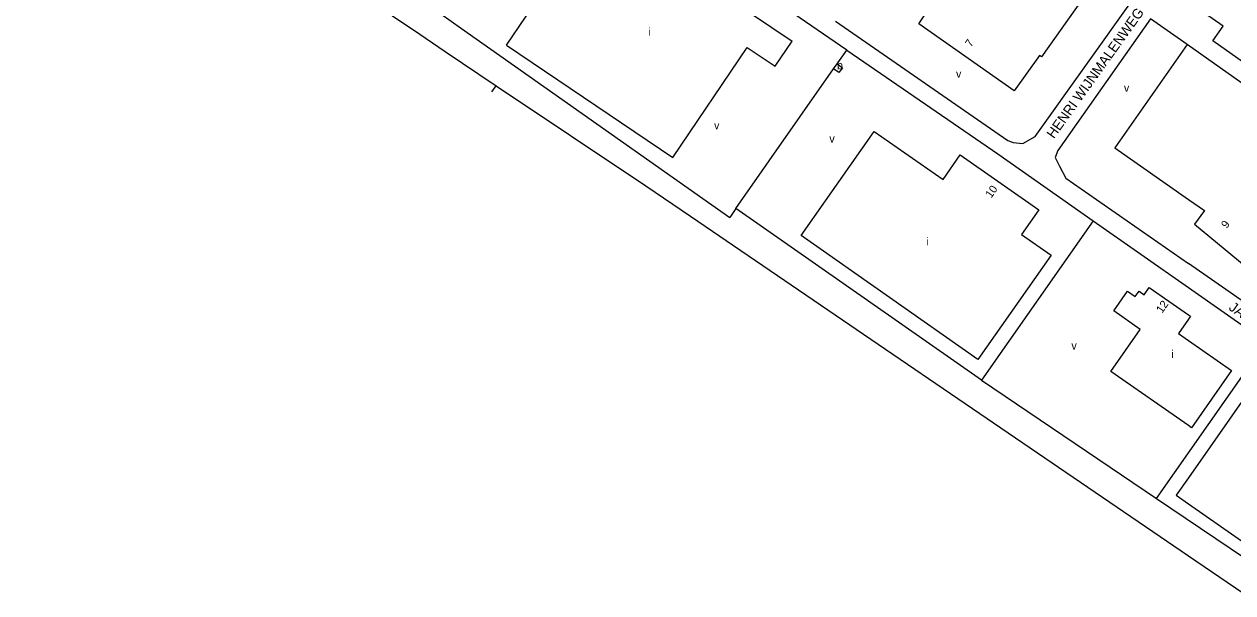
# Model space of a CAD drawing. Extents: x 154765 to 156627, y 383996 to 386132.
# Drawn here: x 154818 to 155422, y 384643 to 384927 of the extents above; entities that cross this region are included whole.
import ezdxf

# ---------------------------------------------------------------- set-up
doc = ezdxf.new("R2010")
doc.units = 0
for name, color, linetype in [('BLT_Basislijn', 7, 'Continuous'), ('BLT_Bebouwing', 7, 'Continuous'), ('BLT_Centroide', 7, 'Continuous'), ('BLT_Huisnummer', 7, 'Continuous'), ('BLT_Huisnummer_reeks', 7, 'Continuous'), ('BLT_Straatnaam', 7, 'Continuous'), ('BLT_Vlakafsluiter', 7, 'Continuous')]:
    doc.layers.add(name, color=color, linetype=linetype)

msp = doc.modelspace()

# ---------------------------------------------------------------- linework, layer by layer
at = {"layer": 'BLT_Basislijn'}
for p, q in [((154818, 385056.39), (155015.72, 384922.31)), ((155229.24, 384914.38), (155092.91, 385008.79)), ((155021.15, 384936.15), (155036.67, 384925.21)), ((155399.36, 384917.11), (155381.05, 384929.95)), ((155036.67, 384925.21), (155157.26, 384840.19)), ((155128.84, 384846.43), (155151.04, 384831.29)), ((155157.26, 384840.19), (155170.71, 384830.71)), ((155173.83, 384835.15), (155170.71, 384830.71)), ((155151.04, 384831.29), (155382.24, 384673.57)), ((155352.48, 384828.91), (155400, 384795.58)), ((155490.88, 384744.23), (155400, 384807.65)), ((155400, 384795.58), (155438.84, 384768.34)), ((155384.1, 384690.1), (155438.84, 384768.34)), ((155296.6, 384749.27), (155384.1, 384690.1)), ((155384.1, 384690.1), (155435.77, 384655.16)), ((155382.24, 384673.57), (155400, 384661.46)), ((155400, 384661.46), (155427.23, 384642.88))]:
    msp.add_line(p, q, dxfattribs=at)
for points in [[(155223.52, 384928.91), (155309.72, 384869.23), (155312.41, 384868.15), (155317.26, 384867.61), (155323.45, 384871.11), (155373.23, 384941.17)], [(155381.05, 384929.95), (155334.76, 384864.11), (155333.42, 384860.6), (155335.57, 384856.29), (155338.8, 384850.37), (155400, 384807.65)], [(155015.72, 384922.31), (155028.45, 384913.68)], [(155028.45, 384913.68), (155053.92, 384896.41)], [(155224.36, 384907.42), (155229.24, 384914.38)], [(155229.24, 384914.38), (155304.71, 384862.41), (155352.48, 384828.91)], [(155173.83, 384835.15), (155222.58, 384904.99)], [(155053.92, 384896.41), (155128.84, 384846.43)], [(155296.6, 384749.27), (155173.83, 384835.15)], [(155352.48, 384828.91), (155296.6, 384749.27)]]:
    msp.add_lwpolyline(points, dxfattribs=at)
at = {"layer": 'BLT_Bebouwing'}
for p, q in [((155059.18, 384916.85), (155103.58, 384982.45)), ((155171.49, 384939.33), (155201.86, 384918.83)), ((155193.41, 384906.34), (155201.86, 384918.83)), ((155059.18, 384916.85), (155142.34, 384860.67)), ((155142.34, 384860.67), (155179.51, 384915.75)), ((155179.51, 384915.75), (155193.41, 384906.34)), ((155222.58, 384904.99), (155224.36, 384907.42))]:
    msp.add_line(p, q, dxfattribs=at)
for points in [[(155357.91, 384955.27), (155326.66, 384910.93), (155325.53, 384911.73), (155312.84, 384894.01), (155265.22, 384927.44), (155268.31, 384932.07), (155247.39, 384946.75), (155287.95, 385004.43)], [(155444.72, 384997.98), (155463.95, 384984.47), (155458.92, 384977.32), (155471.07, 384968.79), (155464.07, 384958.83), (155473.14, 384952.46), (155437.27, 384901.4), (155412.17, 384919.04), (155417.32, 384926.36), (155404.26, 384935.53), (155430.04, 384972.23), (155422.86, 384977.28)], [(155399.36, 384917.11), (155363.2, 384865.52), (155400, 384839.69)], [(155439.29, 384888.96), (155399.36, 384917.11)], [(155224.36, 384907.42), (155227.07, 384905.56), (155225.34, 384903.08), (155222.58, 384904.99)], [(155285.97, 384861.91), (155325.2, 384834.41), (155316.61, 384822.16), (155331.37, 384811.81), (155294.76, 384759.58), (155206.38, 384821.55), (155242.96, 384873.73), (155277.35, 384849.62), (155285.97, 384861.91)], [(155400, 384839.69), (155408.09, 384834.06), (155403.15, 384827.27), (155432.7, 384802.77), (155439.33, 384812.06), (155456.12, 384800.23), (155505.6, 384765.6)], [(155362.67, 384783.95), (155369.6, 384793.83), (155373.4, 384791.12), (155375.33, 384793.83), (155377.96, 384791.99), (155380.47, 384795.59), (155400, 384781.9)], [(155400, 384726.56), (155361.29, 384753.68), (155375.95, 384774.63), (155362.67, 384783.95)], [(155400, 384779.81), (155394.99, 384772.67), (155400, 384769.16)], [(155400, 384781.9), (155400.99, 384781.22), (155400, 384779.81)], [(155400, 384769.16), (155421.52, 384754.12), (155401.51, 384725.5), (155400, 384726.56)], [(155400, 384687.47), (155437.63, 384661.15), (155475.14, 384714.65), (155431.43, 384745.29), (155400, 384700.44)], [(155400, 384700.44), (155393.91, 384691.79)], [(155393.91, 384691.79), (155400, 384687.47)]]:
    msp.add_lwpolyline(points, dxfattribs=at)
at = {"layer": 'BLT_Vlakafsluiter'}
msp.add_line((155051.83, 384893.42), (155053.92, 384896.41), dxfattribs=at)

# ---------------------------------------------------------------- texts
at = {"layer": 'BLT_Centroide'}
for s, p in [('i', (155130.09, 384921.56)), ('b', (155224.36, 384904.77)), ('v', (155283.85, 384900.51)), ('v', (155367.78, 384893.51)), ('v', (155162.89, 384874.74)), ('v', (155220.54, 384868.1)), ('i', (155268.91, 384816.66)), ('v', (155341.54, 384764.57)), ('i', (155391.41, 384760.27))]:
    msp.add_text(s, height=4, dxfattribs=at).set_placement(p)
at = {"layer": 'BLT_Huisnummer'}
for s, rotation, p in [('7', 55.01455, (155291.31, 384915.55)), ('10', 54.96658, (155301.45, 384840.05)), ('12', 54.91899, (155386.85, 384782.44))]:
    msp.add_text(s, height=4, rotation=rotation, dxfattribs=at).set_placement(p)
at = {"layer": 'BLT_Huisnummer_reeks'}
msp.add_text('9', height=4, rotation=54.24527, dxfattribs=at).set_placement((155419.25, 384824.92))
at = {"layer": 'BLT_Straatnaam'}
for s, rotation, p in [('HENRI WIJNMALENWEG', 54.48083, (155332.79, 384869.73)), ('JAN HILGERSWEG', 325.29908, (155419.84, 384784.71))]:
    msp.add_text(s, height=5, rotation=rotation, dxfattribs=at).set_placement(p)

doc.saveas('drawing.dxf')
